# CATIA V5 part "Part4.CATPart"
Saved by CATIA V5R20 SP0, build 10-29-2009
Part number: Part4
Bounding box of the stored display mesh (mm): x -15 to 45, y -20 to 14.999, z 0 to 40
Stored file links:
  E:\Ehsan\CATIA\Tamrin\Digital Mockup\3\Part4.CATPart
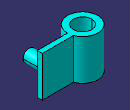
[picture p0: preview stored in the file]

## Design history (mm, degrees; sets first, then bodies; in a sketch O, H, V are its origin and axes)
Body1 (main body)
  Sketch1 on xy-plane, origin (0, 0, 0), H (1, 0, 0), V (0, 1, 0)
    circle A1 centre (0, 0) radius 15
    circle A2 centre (0, 0) radius 9
    radius A1 = 15
    radius A2 = 9
  Pad1: profile Sketch1, direction (0, 0, 1), length 40
  Sketch2 on end face of Pad1, origin (0, 0, 40), H (1, 0, 0), V (0, 1, 0)
    line L1 (15, 0) -> (45, 0)
    line L2 (45, 0) -> (45, 5)
    line L3 (45, 5) -> (14.1421, 5)
    projected circle E1 centre (0, 0) radius 15 from edge [face of Pad1 from Sketch1.A1 | end face of Pad1]
    projected arc E2 centre (0, 0) radius 15 from (15, 0) to (14.1421, 5) ccw from edge [face of Pad1 from Sketch1.A1 | end face of Pad1]
    point P3 (15, 0)
    point P5 (15, 0)
    distance L1 L3 = 5
    horizontal: L1 H, L3 H
    vertical: L2 V
    coincidence: L1 P3, E1 P5, P3 P5
  Pad2: profile Sketch2, direction (0, 0, -1), length 40
  Sketch3 on face of Pad2 from Sketch2.L1, origin (0, 0, 0), H (1, 0, 0), V (0, 0, 1)
    circle A1 centre (33, 20) radius 6
    point P1 (33, 20)
    reference projected line E1 (15, 0) -> (45, 0) from edge [face of Pad2 | face of Pad2 from Sketch2.L1]
    reference projected line E2 (45, 40) -> (45, 0) from edge [face of Pad2 from Sketch2.L1 | face of Pad2 from Sketch2.L2]
    radius A1 = 6
    distance P1 E1 = 20
    distance P1 E2 = 12
  Pad3: profile Sketch3, direction (0, -1, 0), length 20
